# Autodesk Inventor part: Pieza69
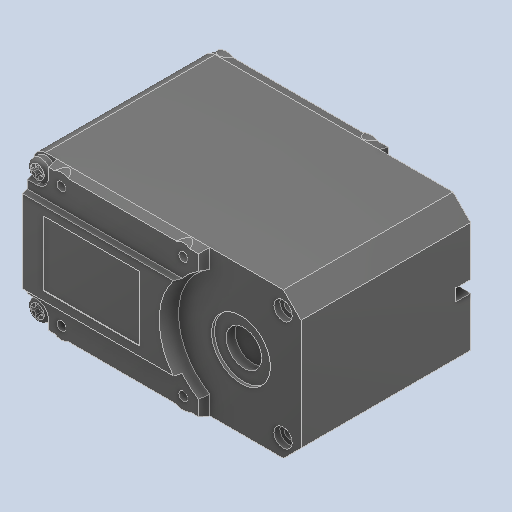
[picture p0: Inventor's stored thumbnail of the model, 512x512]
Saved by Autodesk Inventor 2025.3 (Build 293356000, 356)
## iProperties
Created: 2026-10
Part Number: Pieza69
Material: Genérico
Document SubType Name: Modeling
Designer: Luis M
Density: 1 g/cm^3
Appearance: Valor por defecto
Author: Luis M
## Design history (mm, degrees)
feature "Corps14"
node "Sólido1"
